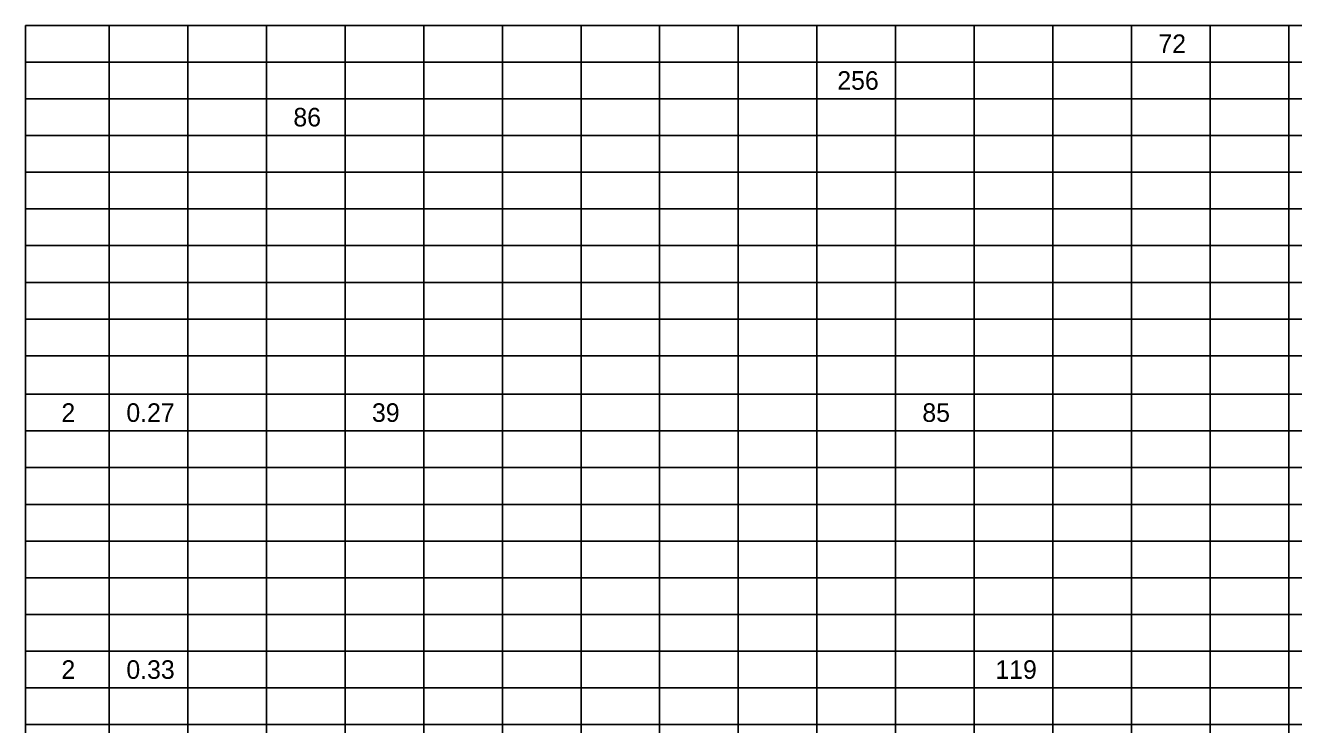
# Model space of a CAD drawing. Extents: x 0.2 to 34.2, y 0 to 22.
# Drawn here: x 14.91 to 24.47, y 10.52 to 15.79 of the extents above; entities that cross this region are included whole.
import ezdxf

# ---------------------------------------------------------------- set-up
doc = ezdxf.new("R2010")
doc.units = 0
doc.layers.add('SH_Text', color=7, linetype='Continuous')

msp = doc.modelspace()

# ---------------------------------------------------------------- linework, layer by layer
at = {"layer": 'SH_Text'}
for p, q in [((14.908, 15.7935), (15.5405, 15.7935)), ((14.908, 15.7935), (14.908, 15.5168)), ((15.5405, 15.7935), (24.4346, 15.7935)), ((15.5405, 15.7935), (15.5405, 15.5168)), ((16.1334, 15.7935), (16.1334, 15.5168)), ((16.7264, 15.7935), (16.7264, 15.5168)), ((17.3193, 15.7935), (17.3193, 15.5168)), ((17.9122, 15.7935), (17.9122, 15.5168)), ((18.5052, 15.7935), (18.5052, 15.5168)), ((19.0981, 15.7935), (19.0981, 15.5168)), ((19.6911, 15.7935), (19.6911, 15.5168)), ((20.284, 15.7935), (20.284, 15.5168)), ((20.8769, 15.7935), (20.8769, 15.5168)), ((21.4699, 15.7935), (21.4699, 15.5168)), ((22.0628, 15.7935), (22.0628, 15.5168)), ((22.6558, 15.7935), (22.6558, 15.5168)), ((23.2487, 15.7935), (23.2487, 15.5168)), ((23.8417, 15.7935), (23.8417, 15.5168)), ((24.4346, 15.7935), (32.1955, 15.7935)), ((24.4346, 15.7935), (24.4346, 15.5168)), ((14.908, 15.5168), (15.5405, 15.5168)), ((14.908, 15.5168), (14.908, 15.2401)), ((15.5405, 15.5168), (24.4346, 15.5168)), ((15.5405, 15.5168), (15.5405, 15.2401)), ((16.1334, 15.5168), (16.1334, 15.2401)), ((16.7264, 15.5168), (16.7264, 15.2401)), ((17.3193, 15.5168), (17.3193, 15.2401)), ((17.9122, 15.5168), (17.9122, 15.2401)), ((18.5052, 15.5168), (18.5052, 15.2401)), ((19.0981, 15.5168), (19.0981, 15.2401)), ((19.6911, 15.5168), (19.6911, 15.2401)), ((20.284, 15.5168), (20.284, 15.2401)), ((20.8769, 15.5168), (20.8769, 15.2401)), ((21.4699, 15.5168), (21.4699, 15.2401)), ((22.0628, 15.5168), (22.0628, 15.2401)), ((22.6558, 15.5168), (22.6558, 15.2401)), ((23.2487, 15.5168), (23.2487, 15.2401)), ((23.8417, 15.5168), (23.8417, 15.2401)), ((24.4346, 15.5168), (32.1955, 15.5168)), ((24.4346, 15.5168), (24.4346, 15.2401)), ((14.908, 15.2401), (15.5405, 15.2401)), ((14.908, 15.2401), (14.908, 14.9634)), ((15.5405, 15.2401), (24.4346, 15.2401)), ((15.5405, 15.2401), (15.5405, 14.9634)), ((16.1334, 15.2401), (16.1334, 14.9634)), ((16.7264, 15.2401), (16.7264, 14.9634)), ((17.3193, 15.2401), (17.3193, 14.9634)), ((17.9122, 15.2401), (17.9122, 14.9634)), ((18.5052, 15.2401), (18.5052, 14.9634)), ((19.0981, 15.2401), (19.0981, 14.9634)), ((19.6911, 15.2401), (19.6911, 14.9634)), ((20.284, 15.2401), (20.284, 14.9634)), ((20.8769, 15.2401), (20.8769, 14.9634)), ((21.4699, 15.2401), (21.4699, 14.9634)), ((22.0628, 15.2401), (22.0628, 14.9634)), ((22.6558, 15.2401), (22.6558, 14.9634)), ((23.2487, 15.2401), (23.2487, 14.9634)), ((23.8417, 15.2401), (23.8417, 14.9634)), ((24.4346, 15.2401), (32.1955, 15.2401)), ((24.4346, 15.2401), (24.4346, 14.9634)), ((14.908, 14.9634), (15.5405, 14.9634)), ((14.908, 14.9634), (14.908, 14.6867)), ((15.5405, 14.9634), (24.4346, 14.9634)), ((15.5405, 14.9634), (15.5405, 14.6867)), ((16.1334, 14.9634), (16.1334, 14.6867)), ((16.7264, 14.9634), (16.7264, 14.6867)), ((17.3193, 14.9634), (17.3193, 14.6867)), ((17.9122, 14.9634), (17.9122, 14.6867)), ((18.5052, 14.9634), (18.5052, 14.6867)), ((19.0981, 14.9634), (19.0981, 14.6867)), ((19.6911, 14.9634), (19.6911, 14.6867)), ((20.284, 14.9634), (20.284, 14.6867)), ((20.8769, 14.9634), (20.8769, 14.6867)), ((21.4699, 14.9634), (21.4699, 14.6867)), ((22.0628, 14.9634), (22.0628, 14.6867)), ((22.6558, 14.9634), (22.6558, 14.6867)), ((23.2487, 14.9634), (23.2487, 14.6867)), ((23.8417, 14.9634), (23.8417, 14.6867)), ((24.4346, 14.9634), (32.1955, 14.9634)), ((24.4346, 14.9634), (24.4346, 14.6867)), ((14.908, 14.6867), (15.5405, 14.6867)), ((14.908, 14.6867), (14.908, 14.41)), ((15.5405, 14.6867), (24.4346, 14.6867)), ((15.5405, 14.6867), (15.5405, 14.41)), ((16.1334, 14.6867), (16.1334, 14.41)), ((16.7264, 14.6867), (16.7264, 14.41)), ((17.3193, 14.6867), (17.3193, 14.41)), ((17.9122, 14.6867), (17.9122, 14.41)), ((18.5052, 14.6867), (18.5052, 14.41)), ((19.0981, 14.6867), (19.0981, 14.41)), ((19.6911, 14.6867), (19.6911, 14.41)), ((20.284, 14.6867), (20.284, 14.41)), ((20.8769, 14.6867), (20.8769, 14.41)), ((21.4699, 14.6867), (21.4699, 14.41)), ((22.0628, 14.6867), (22.0628, 14.41)), ((22.6558, 14.6867), (22.6558, 14.41)), ((23.2487, 14.6867), (23.2487, 14.41)), ((23.8417, 14.6867), (23.8417, 14.41)), ((24.4346, 14.6867), (32.1955, 14.6867)), ((24.4346, 14.6867), (24.4346, 14.41)), ((14.908, 14.41), (15.5405, 14.41)), ((14.908, 14.41), (14.908, 14.1333)), ((15.5405, 14.41), (24.4346, 14.41)), ((15.5405, 14.41), (15.5405, 14.1333)), ((16.1334, 14.41), (16.1334, 14.1333)), ((16.7264, 14.41), (16.7264, 14.1333)), ((17.3193, 14.41), (17.3193, 14.1333)), ((17.9122, 14.41), (17.9122, 14.1333)), ((18.5052, 14.41), (18.5052, 14.1333)), ((19.0981, 14.41), (19.0981, 14.1333)), ((19.6911, 14.41), (19.6911, 14.1333)), ((20.284, 14.41), (20.284, 14.1333)), ((20.8769, 14.41), (20.8769, 14.1333)), ((21.4699, 14.41), (21.4699, 14.1333)), ((22.0628, 14.41), (22.0628, 14.1333)), ((22.6558, 14.41), (22.6558, 14.1333)), ((23.2487, 14.41), (23.2487, 14.1333)), ((23.8417, 14.41), (23.8417, 14.1333)), ((24.4346, 14.41), (32.1955, 14.41)), ((24.4346, 14.41), (24.4346, 14.1333)), ((14.908, 14.1333), (15.5405, 14.1333)), ((14.908, 14.1333), (14.908, 13.8566)), ((15.5405, 14.1333), (24.4346, 14.1333)), ((15.5405, 14.1333), (15.5405, 13.8566)), ((16.1334, 14.1333), (16.1334, 13.8566)), ((16.7264, 14.1333), (16.7264, 13.8566)), ((17.3193, 14.1333), (17.3193, 13.8566)), ((17.9122, 14.1333), (17.9122, 13.8566)), ((18.5052, 14.1333), (18.5052, 13.8566)), ((19.0981, 14.1333), (19.0981, 13.8566)), ((19.6911, 14.1333), (19.6911, 13.8566)), ((20.284, 14.1333), (20.284, 13.8566)), ((20.8769, 14.1333), (20.8769, 13.8566)), ((21.4699, 14.1333), (21.4699, 13.8566)), ((22.0628, 14.1333), (22.0628, 13.8566)), ((22.6558, 14.1333), (22.6558, 13.8566)), ((23.2487, 14.1333), (23.2487, 13.8566)), ((23.8417, 14.1333), (23.8417, 13.8566)), ((24.4346, 14.1333), (32.1955, 14.1333)), ((24.4346, 14.1333), (24.4346, 13.8566)), ((14.908, 13.8566), (15.5405, 13.8566)), ((14.908, 13.8566), (14.908, 13.5799)), ((15.5405, 13.8566), (24.4346, 13.8566)), ((15.5405, 13.8566), (15.5405, 13.5799)), ((16.1334, 13.8566), (16.1334, 13.5799)), ((16.7264, 13.8566), (16.7264, 13.5799)), ((17.3193, 13.8566), (17.3193, 13.5799)), ((17.9122, 13.8566), (17.9122, 13.5799)), ((18.5052, 13.8566), (18.5052, 13.5799)), ((19.0981, 13.8566), (19.0981, 13.5799)), ((19.6911, 13.8566), (19.6911, 13.5799)), ((20.284, 13.8566), (20.284, 13.5799)), ((20.8769, 13.8566), (20.8769, 13.5799)), ((21.4699, 13.8566), (21.4699, 13.5799)), ((22.0628, 13.8566), (22.0628, 13.5799)), ((22.6558, 13.8566), (22.6558, 13.5799)), ((23.2487, 13.8566), (23.2487, 13.5799)), ((23.8417, 13.8566), (23.8417, 13.5799)), ((24.4346, 13.8566), (32.1955, 13.8566)), ((24.4346, 13.8566), (24.4346, 13.5799)), ((14.908, 13.5799), (15.5405, 13.5799)), ((14.908, 13.5799), (14.908, 13.3032)), ((15.5405, 13.5799), (24.4346, 13.5799)), ((15.5405, 13.5799), (15.5405, 13.3032)), ((16.1334, 13.5799), (16.1334, 13.3032)), ((16.7264, 13.5799), (16.7264, 13.3032)), ((17.3193, 13.5799), (17.3193, 13.3032)), ((17.9122, 13.5799), (17.9122, 13.3032)), ((18.5052, 13.5799), (18.5052, 13.3032)), ((19.0981, 13.5799), (19.0981, 13.3032)), ((19.6911, 13.5799), (19.6911, 13.3032)), ((20.284, 13.5799), (20.284, 13.3032)), ((20.8769, 13.5799), (20.8769, 13.3032)), ((21.4699, 13.5799), (21.4699, 13.3032)), ((22.0628, 13.5799), (22.0628, 13.3032)), ((22.6558, 13.5799), (22.6558, 13.3032)), ((23.2487, 13.5799), (23.2487, 13.3032)), ((23.8417, 13.5799), (23.8417, 13.3032)), ((24.4346, 13.5799), (32.1955, 13.5799)), ((24.4346, 13.5799), (24.4346, 13.3032)), ((14.908, 13.3032), (15.5405, 13.3032)), ((14.908, 13.3032), (14.908, 13.0133)), ((15.5405, 13.3032), (24.4346, 13.3032)), ((15.5405, 13.3032), (15.5405, 13.0133)), ((16.1334, 13.3032), (16.1334, 13.0133)), ((16.7264, 13.3032), (16.7264, 13.0133)), ((17.3193, 13.3032), (17.3193, 13.0133)), ((17.9122, 13.3032), (17.9122, 13.0133)), ((18.5052, 13.3032), (18.5052, 13.0133)), ((19.0981, 13.3032), (19.0981, 13.0133)), ((19.6911, 13.3032), (19.6911, 13.0133)), ((20.284, 13.3032), (20.284, 13.0133)), ((20.8769, 13.3032), (20.8769, 13.0133)), ((21.4699, 13.3032), (21.4699, 13.0133)), ((22.0628, 13.3032), (22.0628, 13.0133)), ((22.6558, 13.3032), (22.6558, 13.0133)), ((23.2487, 13.3032), (23.2487, 13.0133)), ((23.8417, 13.3032), (23.8417, 13.0133)), ((24.4346, 13.3032), (32.1955, 13.3032)), ((24.4346, 13.3032), (24.4346, 13.0133)), ((14.908, 13.0133), (15.5405, 13.0133)), ((14.908, 13.0133), (14.908, 12.7366)), ((15.5405, 13.0133), (24.4346, 13.0133)), ((15.5405, 13.0133), (15.5405, 12.7366)), ((16.1334, 13.0133), (16.1334, 12.7366)), ((16.7264, 13.0133), (16.7264, 12.7366)), ((17.3193, 13.0133), (17.3193, 12.7366)), ((17.9122, 13.0133), (17.9122, 12.7366)), ((18.5052, 13.0133), (18.5052, 12.7366)), ((19.0981, 13.0133), (19.0981, 12.7366)), ((19.6911, 13.0133), (19.6911, 12.7366)), ((20.284, 13.0133), (20.284, 12.7366)), ((20.8769, 13.0133), (20.8769, 12.7366)), ((21.4699, 13.0133), (21.4699, 12.7366)), ((22.0628, 13.0133), (22.0628, 12.7366)), ((22.6558, 13.0133), (22.6558, 12.7366)), ((23.2487, 13.0133), (23.2487, 12.7366)), ((23.8417, 13.0133), (23.8417, 12.7366)), ((24.4346, 13.0133), (32.1955, 13.0133)), ((24.4346, 13.0133), (24.4346, 12.7366)), ((14.908, 12.7366), (15.5405, 12.7366)), ((14.908, 12.7366), (14.908, 12.4599)), ((15.5405, 12.7366), (24.4346, 12.7366)), ((15.5405, 12.7366), (15.5405, 12.4599)), ((16.1334, 12.7366), (16.1334, 12.4599)), ((16.7264, 12.7366), (16.7264, 12.4599)), ((17.3193, 12.7366), (17.3193, 12.4599)), ((17.9122, 12.7366), (17.9122, 12.4599)), ((18.5052, 12.7366), (18.5052, 12.4599)), ((19.0981, 12.7366), (19.0981, 12.4599)), ((19.6911, 12.7366), (19.6911, 12.4599)), ((20.284, 12.7366), (20.284, 12.4599)), ((20.8769, 12.7366), (20.8769, 12.4599)), ((21.4699, 12.7366), (21.4699, 12.4599)), ((22.0628, 12.7366), (22.0628, 12.4599)), ((22.6558, 12.7366), (22.6558, 12.4599)), ((23.2487, 12.7366), (23.2487, 12.4599)), ((23.8417, 12.7366), (23.8417, 12.4599)), ((24.4346, 12.7366), (32.1955, 12.7366)), ((24.4346, 12.7366), (24.4346, 12.4599)), ((14.908, 12.4599), (15.5405, 12.4599)), ((14.908, 12.4599), (14.908, 12.1831)), ((15.5405, 12.4599), (24.4346, 12.4599)), ((15.5405, 12.4599), (15.5405, 12.1831)), ((16.1334, 12.4599), (16.1334, 12.1831)), ((16.7264, 12.4599), (16.7264, 12.1831)), ((17.3193, 12.4599), (17.3193, 12.1831)), ((17.9122, 12.4599), (17.9122, 12.1831)), ((18.5052, 12.4599), (18.5052, 12.1831)), ((19.0981, 12.4599), (19.0981, 12.1831)), ((19.6911, 12.4599), (19.6911, 12.1831)), ((20.284, 12.4599), (20.284, 12.1831)), ((20.8769, 12.4599), (20.8769, 12.1831)), ((21.4699, 12.4599), (21.4699, 12.1831)), ((22.0628, 12.4599), (22.0628, 12.1831)), ((22.6558, 12.4599), (22.6558, 12.1831)), ((23.2487, 12.4599), (23.2487, 12.1831)), ((23.8417, 12.4599), (23.8417, 12.1831)), ((24.4346, 12.4599), (32.1955, 12.4599)), ((24.4346, 12.4599), (24.4346, 12.1831)), ((14.908, 12.1831), (15.5405, 12.1831)), ((14.908, 12.1831), (14.908, 11.9064)), ((15.5405, 12.1831), (24.4346, 12.1831)), ((15.5405, 12.1831), (15.5405, 11.9064)), ((16.1334, 12.1831), (16.1334, 11.9064)), ((16.7264, 12.1831), (16.7264, 11.9064)), ((17.3193, 12.1831), (17.3193, 11.9064)), ((17.9122, 12.1831), (17.9122, 11.9064)), ((18.5052, 12.1831), (18.5052, 11.9064)), ((19.0981, 12.1831), (19.0981, 11.9064)), ((19.6911, 12.1831), (19.6911, 11.9064)), ((20.284, 12.1831), (20.284, 11.9064)), ((20.8769, 12.1831), (20.8769, 11.9064)), ((21.4699, 12.1831), (21.4699, 11.9064)), ((22.0628, 12.1831), (22.0628, 11.9064)), ((22.6558, 12.1831), (22.6558, 11.9064)), ((23.2487, 12.1831), (23.2487, 11.9064)), ((23.8417, 12.1831), (23.8417, 11.9064)), ((24.4346, 12.1831), (32.1955, 12.1831)), ((24.4346, 12.1831), (24.4346, 11.9064)), ((14.908, 11.9064), (15.5405, 11.9064)), ((14.908, 11.9064), (14.908, 11.6297)), ((15.5405, 11.9064), (24.4346, 11.9064)), ((15.5405, 11.9064), (15.5405, 11.6297)), ((16.1334, 11.9064), (16.1334, 11.6297)), ((16.7264, 11.9064), (16.7264, 11.6297)), ((17.3193, 11.9064), (17.3193, 11.6297)), ((17.9122, 11.9064), (17.9122, 11.6297)), ((18.5052, 11.9064), (18.5052, 11.6297)), ((19.0981, 11.9064), (19.0981, 11.6297)), ((19.6911, 11.9064), (19.6911, 11.6297)), ((20.284, 11.9064), (20.284, 11.6297)), ((20.8769, 11.9064), (20.8769, 11.6297)), ((21.4699, 11.9064), (21.4699, 11.6297)), ((22.0628, 11.9064), (22.0628, 11.6297)), ((22.6558, 11.9064), (22.6558, 11.6297)), ((23.2487, 11.9064), (23.2487, 11.6297)), ((23.8417, 11.9064), (23.8417, 11.6297)), ((24.4346, 11.9064), (32.1955, 11.9064)), ((24.4346, 11.9064), (24.4346, 11.6297)), ((14.908, 11.6297), (15.5405, 11.6297)), ((14.908, 11.6297), (14.908, 11.353)), ((15.5405, 11.6297), (24.4346, 11.6297)), ((15.5405, 11.6297), (15.5405, 11.353)), ((16.1334, 11.6297), (16.1334, 11.353)), ((16.7264, 11.6297), (16.7264, 11.353)), ((17.3193, 11.6297), (17.3193, 11.353)), ((17.9122, 11.6297), (17.9122, 11.353)), ((18.5052, 11.6297), (18.5052, 11.353)), ((19.0981, 11.6297), (19.0981, 11.353)), ((19.6911, 11.6297), (19.6911, 11.353)), ((20.284, 11.6297), (20.284, 11.353)), ((20.8769, 11.6297), (20.8769, 11.353)), ((21.4699, 11.6297), (21.4699, 11.353)), ((22.0628, 11.6297), (22.0628, 11.353)), ((22.6558, 11.6297), (22.6558, 11.353)), ((23.2487, 11.6297), (23.2487, 11.353)), ((23.8417, 11.6297), (23.8417, 11.353)), ((24.4346, 11.6297), (32.1955, 11.6297)), ((24.4346, 11.6297), (24.4346, 11.353)), ((14.908, 11.353), (15.5405, 11.353)), ((14.908, 11.353), (14.908, 11.0763)), ((15.5405, 11.353), (24.4346, 11.353)), ((15.5405, 11.353), (15.5405, 11.0763)), ((16.1334, 11.353), (16.1334, 11.0763)), ((16.7264, 11.353), (16.7264, 11.0763)), ((17.3193, 11.353), (17.3193, 11.0763)), ((17.9122, 11.353), (17.9122, 11.0763)), ((18.5052, 11.353), (18.5052, 11.0763)), ((19.0981, 11.353), (19.0981, 11.0763)), ((19.6911, 11.353), (19.6911, 11.0763)), ((20.284, 11.353), (20.284, 11.0763)), ((20.8769, 11.353), (20.8769, 11.0763)), ((21.4699, 11.353), (21.4699, 11.0763)), ((22.0628, 11.353), (22.0628, 11.0763)), ((22.6558, 11.353), (22.6558, 11.0763)), ((23.2487, 11.353), (23.2487, 11.0763)), ((23.8417, 11.353), (23.8417, 11.0763)), ((24.4346, 11.353), (32.1955, 11.353)), ((24.4346, 11.353), (24.4346, 11.0763)), ((14.908, 11.0763), (15.5405, 11.0763)), ((14.908, 11.0763), (14.908, 10.7996)), ((15.5405, 11.0763), (24.4346, 11.0763)), ((15.5405, 11.0763), (15.5405, 10.7996)), ((16.1334, 11.0763), (16.1334, 10.7996)), ((16.7264, 11.0763), (16.7264, 10.7996)), ((17.3193, 11.0763), (17.3193, 10.7996)), ((17.9122, 11.0763), (17.9122, 10.7996)), ((18.5052, 11.0763), (18.5052, 10.7996)), ((19.0981, 11.0763), (19.0981, 10.7996)), ((19.6911, 11.0763), (19.6911, 10.7996)), ((20.284, 11.0763), (20.284, 10.7996)), ((20.8769, 11.0763), (20.8769, 10.7996)), ((21.4699, 11.0763), (21.4699, 10.7996)), ((22.0628, 11.0763), (22.0628, 10.7996)), ((22.6558, 11.0763), (22.6558, 10.7996)), ((23.2487, 11.0763), (23.2487, 10.7996)), ((23.8417, 11.0763), (23.8417, 10.7996)), ((24.4346, 11.0763), (32.1955, 11.0763)), ((24.4346, 11.0763), (24.4346, 10.7996)), ((14.908, 10.7996), (15.5405, 10.7996)), ((14.908, 10.7996), (14.908, 10.5229)), ((15.5405, 10.7996), (24.4346, 10.7996)), ((15.5405, 10.7996), (15.5405, 10.5229)), ((16.1334, 10.7996), (16.1334, 10.5229)), ((16.7264, 10.7996), (16.7264, 10.5229)), ((17.3193, 10.7996), (17.3193, 10.5229)), ((17.9122, 10.7996), (17.9122, 10.5229)), ((18.5052, 10.7996), (18.5052, 10.5229)), ((19.0981, 10.7996), (19.0981, 10.5229)), ((19.6911, 10.7996), (19.6911, 10.5229)), ((20.284, 10.7996), (20.284, 10.5229)), ((20.8769, 10.7996), (20.8769, 10.5229)), ((21.4699, 10.7996), (21.4699, 10.5229)), ((22.0628, 10.7996), (22.0628, 10.5229)), ((22.6558, 10.7996), (22.6558, 10.5229)), ((23.2487, 10.7996), (23.2487, 10.5229)), ((23.8417, 10.7996), (23.8417, 10.5229)), ((24.4346, 10.7996), (32.1955, 10.7996)), ((24.4346, 10.7996), (24.4346, 10.5229)), ((14.908, 10.5229), (15.5405, 10.5229)), ((14.908, 10.5229), (14.908, 10.233)), ((15.5405, 10.5229), (24.4346, 10.5229)), ((15.5405, 10.5229), (15.5405, 10.233)), ((16.1334, 10.5229), (16.1334, 10.233)), ((16.7264, 10.5229), (16.7264, 10.233)), ((17.3193, 10.5229), (17.3193, 10.233)), ((17.9122, 10.5229), (17.9122, 10.233)), ((18.5052, 10.5229), (18.5052, 10.233)), ((19.0981, 10.5229), (19.0981, 10.233)), ((19.6911, 10.5229), (19.6911, 10.233)), ((20.284, 10.5229), (20.284, 10.233)), ((20.8769, 10.5229), (20.8769, 10.233)), ((21.4699, 10.5229), (21.4699, 10.233)), ((22.0628, 10.5229), (22.0628, 10.233)), ((22.6558, 10.5229), (22.6558, 10.233)), ((23.2487, 10.5229), (23.2487, 10.233)), ((23.8417, 10.5229), (23.8417, 10.233)), ((24.4346, 10.5229), (32.1955, 10.5229)), ((24.4346, 10.5229), (24.4346, 10.233))]:
    msp.add_line(p, q, dxfattribs=at)

# ---------------------------------------------------------------- texts
for s, p in [('72', (23.452, 15.5852)), ('256', (21.0306, 15.3084)), ('86', (16.929, 15.0317)), ('2', (15.18, 12.8049)), ('0.27', (15.6697, 12.8049)), ('39', (17.5218, 12.8049)), ('85', (21.672, 12.8049)), ('2', (15.18, 10.868)), ('0.33', (15.6697, 10.868)), ('119', (22.2229, 10.868))]:
    msp.add_text(s, height=0.14, dxfattribs=at).set_placement(p)

doc.saveas('drawing.dxf')
